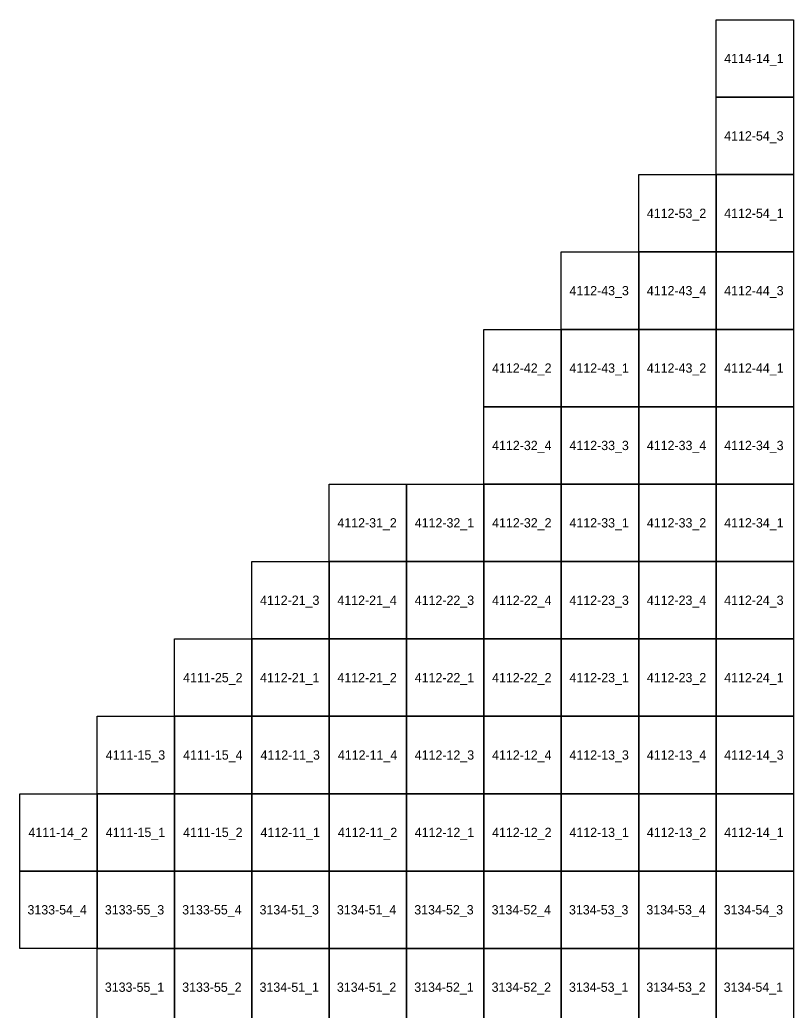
# Model space of a CAD drawing. Extents: x 312500 to 765000, y 172500 to 440000.
# Drawn here: x 317500 to 342332, y 295507 to 327500 of the extents above; entities that cross this region are included whole.
import ezdxf

# ---------------------------------------------------------------- set-up
doc = ezdxf.new("R2010")
doc.units = 0
doc.layers.add('Topo5_ramis_TKS2025', color=7, linetype='Continuous')
doc.layers.add('Topo5_ramis_TKS2025_Nr', color=7, linetype='Continuous')

msp = doc.modelspace()

# ---------------------------------------------------------------- linework, layer by layer
at = {"layer": 'Topo5_ramis_TKS2025'}
for points in [[(340000, 325000), (340000, 327500), (342500, 327500), (342500, 325000), (340000, 325000)], [(340000, 322500), (340000, 325000), (342500, 325000), (342500, 322500), (340000, 322500)], [(337500, 320000), (337500, 322500), (340000, 322500), (340000, 320000), (337500, 320000)], [(340000, 320000), (340000, 322500), (342500, 322500), (342500, 320000), (340000, 320000)], [(335000, 317500), (335000, 320000), (337500, 320000), (337500, 317500), (335000, 317500)], [(337500, 317500), (337500, 320000), (340000, 320000), (340000, 317500), (337500, 317500)], [(340000, 317500), (340000, 320000), (342500, 320000), (342500, 317500), (340000, 317500)], [(332500, 315000), (332500, 317500), (335000, 317500), (335000, 315000), (332500, 315000)], [(335000, 315000), (335000, 317500), (337500, 317500), (337500, 315000), (335000, 315000)], [(337500, 315000), (337500, 317500), (340000, 317500), (340000, 315000), (337500, 315000)], [(340000, 315000), (340000, 317500), (342500, 317500), (342500, 315000), (340000, 315000)], [(332500, 312500), (332500, 315000), (335000, 315000), (335000, 312500), (332500, 312500)], [(335000, 312500), (335000, 315000), (337500, 315000), (337500, 312500), (335000, 312500)], [(337500, 312500), (337500, 315000), (340000, 315000), (340000, 312500), (337500, 312500)], [(340000, 312500), (340000, 315000), (342500, 315000), (342500, 312500), (340000, 312500)], [(327500, 310000), (327500, 312500), (330000, 312500), (330000, 310000), (327500, 310000)], [(330000, 310000), (330000, 312500), (332500, 312500), (332500, 310000), (330000, 310000)], [(332500, 310000), (332500, 312500), (335000, 312500), (335000, 310000), (332500, 310000)], [(335000, 310000), (335000, 312500), (337500, 312500), (337500, 310000), (335000, 310000)], [(337500, 310000), (337500, 312500), (340000, 312500), (340000, 310000), (337500, 310000)], [(340000, 310000), (340000, 312500), (342500, 312500), (342500, 310000), (340000, 310000)], [(325000, 307500), (325000, 310000), (327500, 310000), (327500, 307500), (325000, 307500)], [(327500, 307500), (327500, 310000), (330000, 310000), (330000, 307500), (327500, 307500)], [(330000, 307500), (330000, 310000), (332500, 310000), (332500, 307500), (330000, 307500)], [(332500, 307500), (332500, 310000), (335000, 310000), (335000, 307500), (332500, 307500)], [(335000, 307500), (335000, 310000), (337500, 310000), (337500, 307500), (335000, 307500)], [(337500, 307500), (337500, 310000), (340000, 310000), (340000, 307500), (337500, 307500)], [(340000, 307500), (340000, 310000), (342500, 310000), (342500, 307500), (340000, 307500)], [(322500, 305000), (322500, 307500), (325000, 307500), (325000, 305000), (322500, 305000)], [(325000, 305000), (325000, 307500), (327500, 307500), (327500, 305000), (325000, 305000)], [(327500, 305000), (327500, 307500), (330000, 307500), (330000, 305000), (327500, 305000)], [(330000, 305000), (330000, 307500), (332500, 307500), (332500, 305000), (330000, 305000)], [(332500, 305000), (332500, 307500), (335000, 307500), (335000, 305000), (332500, 305000)], [(335000, 305000), (335000, 307500), (337500, 307500), (337500, 305000), (335000, 305000)], [(337500, 305000), (337500, 307500), (340000, 307500), (340000, 305000), (337500, 305000)], [(340000, 305000), (340000, 307500), (342500, 307500), (342500, 305000), (340000, 305000)], [(320000, 302500), (320000, 305000), (322500, 305000), (322500, 302500), (320000, 302500)], [(322500, 302500), (322500, 305000), (325000, 305000), (325000, 302500), (322500, 302500)], [(325000, 302500), (325000, 305000), (327500, 305000), (327500, 302500), (325000, 302500)], [(327500, 302500), (327500, 305000), (330000, 305000), (330000, 302500), (327500, 302500)], [(330000, 302500), (330000, 305000), (332500, 305000), (332500, 302500), (330000, 302500)], [(332500, 302500), (332500, 305000), (335000, 305000), (335000, 302500), (332500, 302500)], [(335000, 302500), (335000, 305000), (337500, 305000), (337500, 302500), (335000, 302500)], [(337500, 302500), (337500, 305000), (340000, 305000), (340000, 302500), (337500, 302500)], [(340000, 302500), (340000, 305000), (342500, 305000), (342500, 302500), (340000, 302500)], [(317500, 300000), (317500, 302500), (320000, 302500), (320000, 300000), (317500, 300000)], [(320000, 300000), (320000, 302500), (322500, 302500), (322500, 300000), (320000, 300000)], [(322500, 300000), (322500, 302500), (325000, 302500), (325000, 300000), (322500, 300000)], [(325000, 300000), (325000, 302500), (327500, 302500), (327500, 300000), (325000, 300000)], [(327500, 300000), (327500, 302500), (330000, 302500), (330000, 300000), (327500, 300000)], [(330000, 300000), (330000, 302500), (332500, 302500), (332500, 300000), (330000, 300000)], [(332500, 300000), (332500, 302500), (335000, 302500), (335000, 300000), (332500, 300000)], [(335000, 300000), (335000, 302500), (337500, 302500), (337500, 300000), (335000, 300000)], [(337500, 300000), (337500, 302500), (340000, 302500), (340000, 300000), (337500, 300000)], [(340000, 300000), (340000, 302500), (342500, 302500), (342500, 300000), (340000, 300000)], [(317500, 297500), (317500, 300000), (320000, 300000), (320000, 297500), (317500, 297500)], [(320000, 297500), (320000, 300000), (322500, 300000), (322500, 297500), (320000, 297500)], [(322500, 297500), (322500, 300000), (325000, 300000), (325000, 297500), (322500, 297500)], [(325000, 297500), (325000, 300000), (327500, 300000), (327500, 297500), (325000, 297500)], [(327500, 297500), (327500, 300000), (330000, 300000), (330000, 297500), (327500, 297500)], [(330000, 297500), (330000, 300000), (332500, 300000), (332500, 297500), (330000, 297500)], [(332500, 297500), (332500, 300000), (335000, 300000), (335000, 297500), (332500, 297500)], [(335000, 297500), (335000, 300000), (337500, 300000), (337500, 297500), (335000, 297500)], [(337500, 297500), (337500, 300000), (340000, 300000), (340000, 297500), (337500, 297500)], [(340000, 297500), (340000, 300000), (342500, 300000), (342500, 297500), (340000, 297500)], [(320000, 295000), (320000, 297500), (322500, 297500), (322500, 295000), (320000, 295000)], [(322500, 295000), (322500, 297500), (325000, 297500), (325000, 295000), (322500, 295000)], [(325000, 295000), (325000, 297500), (327500, 297500), (327500, 295000), (325000, 295000)], [(327500, 295000), (327500, 297500), (330000, 297500), (330000, 295000), (327500, 295000)], [(330000, 295000), (330000, 297500), (332500, 297500), (332500, 295000), (330000, 295000)], [(332500, 295000), (332500, 297500), (335000, 297500), (335000, 295000), (332500, 295000)], [(335000, 295000), (335000, 297500), (337500, 297500), (337500, 295000), (335000, 295000)], [(337500, 295000), (337500, 297500), (340000, 297500), (340000, 295000), (337500, 295000)], [(340000, 295000), (340000, 297500), (342500, 297500), (342500, 295000), (340000, 295000)]]:
    msp.add_lwpolyline(points, dxfattribs=at)

# ---------------------------------------------------------------- texts
at = {"layer": 'Topo5_ramis_TKS2025_Nr'}
for s, p in [('4114-14_1', (340264, 326100)), ('4112-54_3', (340264, 323600)), ('4112-53_2', (337764, 321100)), ('4112-54_1', (340264, 321100)), ('4112-43_3', (335264, 318600)), ('4112-43_4', (337764, 318600)), ('4112-44_3', (340264, 318600)), ('4112-42_2', (332764, 316100)), ('4112-43_1', (335264, 316100)), ('4112-43_2', (337764, 316100)), ('4112-44_1', (340264, 316100)), ('4112-32_4', (332764, 313600)), ('4112-33_3', (335264, 313600)), ('4112-33_4', (337764, 313600)), ('4112-34_3', (340264, 313600)), ('4112-31_2', (327764, 311100)), ('4112-32_1', (330264, 311100)), ('4112-32_2', (332764, 311100)), ('4112-33_1', (335264, 311100)), ('4112-33_2', (337764, 311100)), ('4112-34_1', (340264, 311100)), ('4112-21_3', (325264, 308600)), ('4112-21_4', (327764, 308600)), ('4112-22_3', (330264, 308600)), ('4112-22_4', (332764, 308600)), ('4112-23_3', (335264, 308600)), ('4112-23_4', (337764, 308600)), ('4112-24_3', (340264, 308600)), ('4111-25_2', (322779, 306100)), ('4112-21_1', (325264, 306100)), ('4112-21_2', (327764, 306100)), ('4112-22_1', (330264, 306100)), ('4112-22_2', (332764, 306100)), ('4112-23_1', (335264, 306100)), ('4112-23_2', (337764, 306100)), ('4112-24_1', (340264, 306100)), ('4111-15_3', (320279, 303600)), ('4111-15_4', (322779, 303600)), ('4112-11_3', (325279, 303600)), ('4112-11_4', (327779, 303600)), ('4112-12_3', (330264, 303600)), ('4112-12_4', (332764, 303600)), ('4112-13_3', (335264, 303600)), ('4112-13_4', (337764, 303600)), ('4112-14_3', (340264, 303600)), ('4111-14_2', (317779, 301100)), ('4111-15_1', (320279, 301100)), ('4111-15_2', (322779, 301100)), ('4112-11_1', (325279, 301100)), ('4112-11_2', (327779, 301100)), ('4112-12_1', (330264, 301100)), ('4112-12_2', (332764, 301100)), ('4112-13_1', (335264, 301100)), ('4112-13_2', (337764, 301100)), ('4112-14_1', (340264, 301100)), ('3133-54_4', (317748, 298600)), ('3133-55_3', (320248, 298600)), ('3133-55_4', (322748, 298600)), ('3134-51_3', (325248, 298600)), ('3134-51_4', (327748, 298600)), ('3134-52_3', (330248, 298600)), ('3134-52_4', (332748, 298600)), ('3134-53_3', (335248, 298600)), ('3134-53_4', (337748, 298600)), ('3134-54_3', (340248, 298600)), ('3133-55_1', (320248, 296100)), ('3133-55_2', (322748, 296100)), ('3134-51_1', (325248, 296100)), ('3134-51_2', (327748, 296100)), ('3134-52_1', (330248, 296100)), ('3134-52_2', (332748, 296100)), ('3134-53_1', (335248, 296100)), ('3134-53_2', (337748, 296100)), ('3134-54_1', (340248, 296100))]:
    msp.add_text(s, height=300, dxfattribs=at).set_placement(p)

doc.saveas('drawing.dxf')
